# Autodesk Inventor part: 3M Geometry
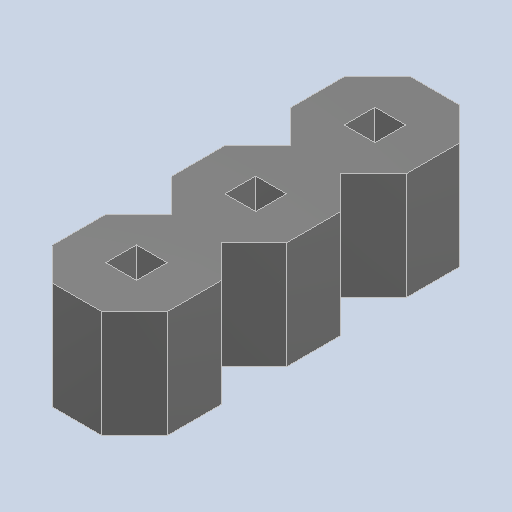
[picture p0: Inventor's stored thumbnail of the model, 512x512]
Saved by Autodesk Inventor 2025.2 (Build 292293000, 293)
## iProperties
Created: 2025-04
Part Number: 3M Geometry
Material: Generic
Description: PART-3M Geometry-DESC
Document SubType Name: Modeling
Designer: BennF
Density: 1 g/cm^3
Appearance: Default
Author: BennF
Revision Number: NONE
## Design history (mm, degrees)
feature "4"
body "Solid1"
